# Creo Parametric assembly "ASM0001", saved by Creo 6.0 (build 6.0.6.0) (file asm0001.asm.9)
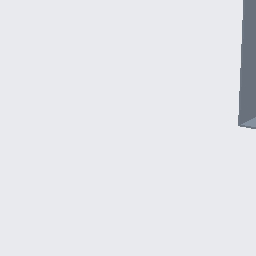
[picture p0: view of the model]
Units: Inch lbm Second (Pro/E Default); INCH, POUND, SECS

Created from: INLBS_ASM_DESIGN.ASM

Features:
  1. datum plane "ASM_RIGHT"
  2. datum plane "ASM_TOP"
  3. datum plane "ASM_FRONT"
  4. coordinate system
  5. component "PRT0001"
  6. component "LEFT"
  7. coordinate system
  8. component "BACK"
  9. component "PRT0002"
  10. component "RIGHT"

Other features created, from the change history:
  component "BACK.PRT"
  component "RIGHT.PRT"
  component "PRT0002.PRT"

Other named items: ACS4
